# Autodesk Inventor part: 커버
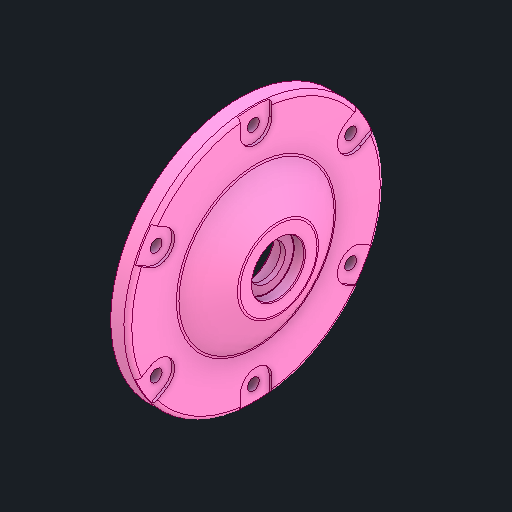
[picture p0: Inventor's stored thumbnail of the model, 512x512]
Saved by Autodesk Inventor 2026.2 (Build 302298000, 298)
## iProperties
Created: 2025-11
Part Number: 커버
Material: 알루미늄 6061
Document SubType Name: Modeling
Designer: PC2-07
Density: 2.7 g/cm^3
Appearance: 기본값
Author: jhkim
Sending System: Autodesk Inventor 2026
Preprocessor: ST-DEVELOPER v20.1
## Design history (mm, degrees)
feature "솔리드1"
node "솔리드2"
